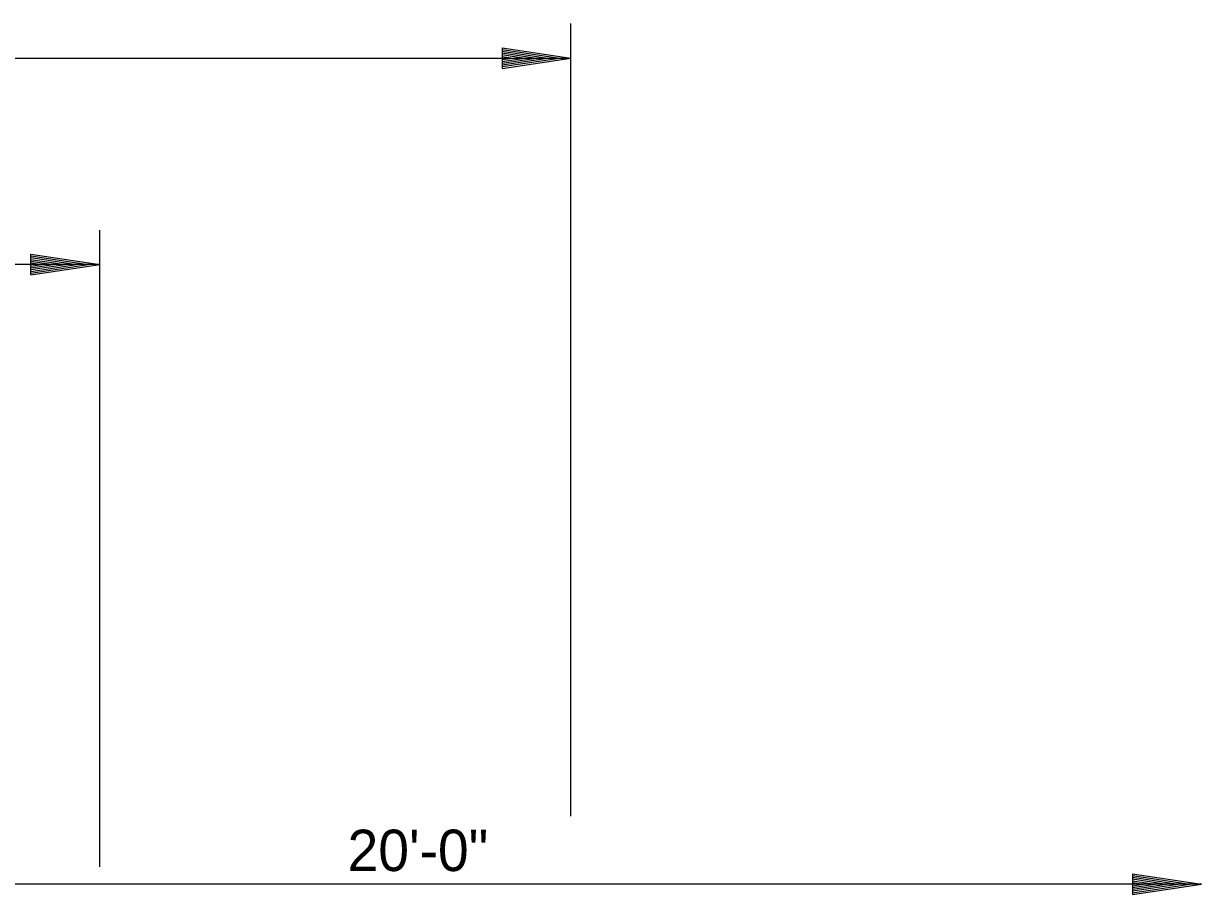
# Model space of a CAD drawing. Extents: x -900 to 15312, y 1857 to 2945.
# Drawn here: x 4203.1 to 4374.2, y 2524.5 to 2651 of the extents above; entities that cross this region are included whole.
import ezdxf

# ---------------------------------------------------------------- set-up
doc = ezdxf.new("R2010")
doc.units = 0
doc.layers.add('R_Annotation', color=7, linetype='Continuous')
doc.layers.add('R_Dimension', color=7, linetype='Continuous')

msp = doc.modelspace()

# ---------------------------------------------------------------- linework, layer by layer
at = {"layer": 'R_Dimension'}
for p, q in [((4282.59, 2535.88), (4282.59, 2651.02)), ((4272.59, 2647.52), (4282.59, 2646.02)), ((4272.59, 2647.52), (4272.59, 2644.52)), ((4272.59, 2647.27), (4280.92, 2646.02)), ((4272.59, 2647.02), (4279.2, 2646.02)), ((4272.59, 2646.77), (4277.53, 2646.02)), ((4272.59, 2646.51), (4275.84, 2646.02)), ((3845.74, 2646.02), (4282.59, 2646.02)), ((4272.59, 2646.26), (4274.17, 2646.02)), ((4272.59, 2644.52), (4282.59, 2646.02)), ((4272.59, 2645.53), (4275.84, 2646.02)), ((4272.59, 2645.03), (4279.2, 2646.02)), ((4272.59, 2644.77), (4280.92, 2646.02)), ((4272.59, 2645.28), (4277.53, 2646.02)), ((4272.59, 2645.79), (4274.17, 2646.02)), ((4214.16, 2528.52), (4214.16, 2621.02)), ((4204.16, 2617.52), (4214.16, 2616.02)), ((4204.16, 2614.52), (4204.16, 2617.52)), ((4214.16, 2616.02), (3914.16, 2616.02)), ((4204.16, 2617.27), (4212.49, 2616.02)), ((4204.16, 2617.02), (4210.77, 2616.02)), ((4204.16, 2616.77), (4209.11, 2616.02)), ((4204.16, 2616.51), (4207.41, 2616.02)), ((4204.16, 2616.26), (4205.74, 2616.02)), ((4204.16, 2614.52), (4214.16, 2616.02)), ((4204.16, 2615.54), (4207.41, 2616.02)), ((4204.16, 2615.03), (4210.77, 2616.02)), ((4204.16, 2614.77), (4212.49, 2616.02)), ((4204.16, 2615.28), (4209.11, 2616.02)), ((4204.16, 2615.79), (4205.74, 2616.02)), ((4364.16, 2527.52), (4374.16, 2526.02)), ((4364.16, 2527.52), (4364.16, 2524.52)), ((4364.16, 2527.27), (4372.49, 2526.02)), ((4364.16, 2527.02), (4370.77, 2526.02)), ((4364.16, 2526.77), (4369.11, 2526.02)), ((4374.16, 2526.02), (4174.16, 2526.02)), ((4364.16, 2526.51), (4367.41, 2526.02)), ((4364.16, 2526.26), (4365.74, 2526.02)), ((4364.16, 2524.52), (4374.16, 2526.02)), ((4364.16, 2525.53), (4367.41, 2526.02)), ((4364.16, 2525.03), (4370.77, 2526.02)), ((4364.16, 2524.77), (4372.49, 2526.02)), ((4364.16, 2525.28), (4369.11, 2526.02)), ((4364.16, 2525.79), (4365.74, 2526.02))]:
    msp.add_line(p, q, dxfattribs=at)

# ---------------------------------------------------------------- texts
at = {"layer": 'R_Annotation'}
msp.add_text('20\'-0"', height=6, dxfattribs=at).set_placement((4250.15, 2527.93))

doc.saveas('drawing.dxf')
